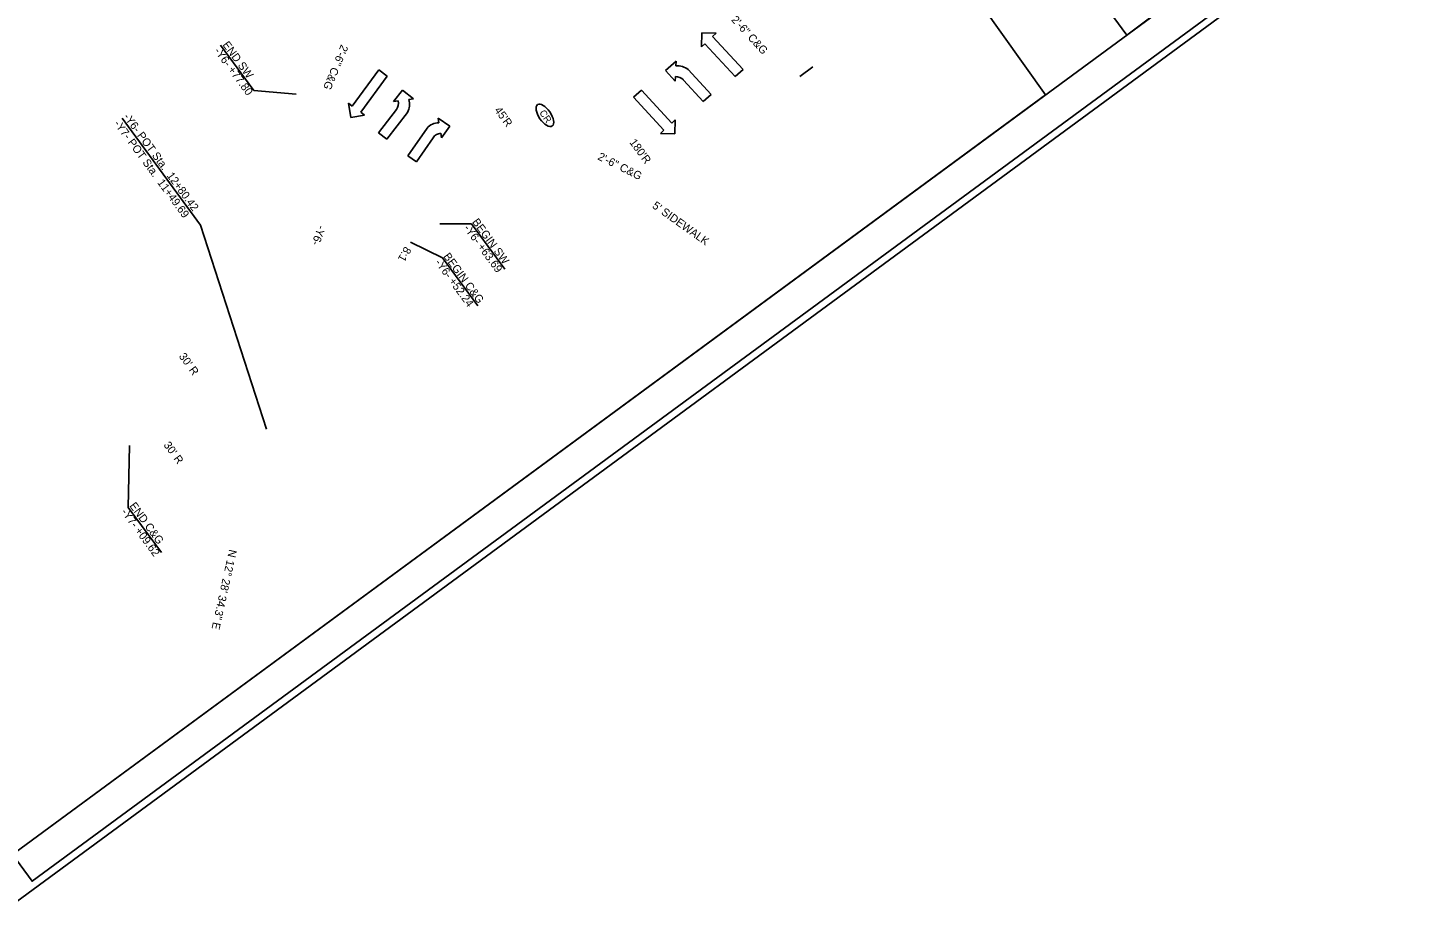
# Model space of a CAD drawing. Extents: x 1763480 to 1764420, y 711010 to 712012.
# Drawn here: x 1763983.9 to 1764419.6, y 711009.7 to 711284 of the extents above; entities that cross this region are included whole.
import ezdxf

# ---------------------------------------------------------------- set-up
doc = ezdxf.new("R2010")
doc.units = 0
for name, color, linetype in [('Old_Level_40', 7, 'Continuous'), ('P-WATER', 7, 'Continuous'), ('Prop Conc 4in Sidewalk', 7, 'Continuous'), ('Prop Grid Mask', 7, 'Continuous'), ('Prop Horizontal Alignment Direction Label', 7, 'Continuous'), ('Prop Horizontal Alignment Station Label', 7, 'Continuous'), ('Prop Lane Arrow CELL', 7, 'Continuous'), ('Prop Rem of Exist Asph Pvmt', 7, 'Continuous'), ('Prop WCC CELL', 7, 'Continuous'), ('Sheet Plot Border Inside CELL', 7, 'Continuous'), ('Sheet Plot Border Outside CELL', 7, 'Continuous')]:
    doc.layers.add(name, color=color, linetype=linetype)

msp = doc.modelspace()

# ---------------------------------------------------------------- linework, layer by layer
at = {"layer": 'Old_Level_40'}
msp.add_lwpolyline([(1764268.03, 711362.41), (1764327.28, 711281.82), (1764337.34, 711289.22), (1764278.09, 711369.81)], close=True, dxfattribs=at)
at = {"layer": 'P-WATER'}
msp.add_lwpolyline([(1764402.04, 711336.79), (1763957.77, 711941.04), (1763535.55, 711630.61), (1763979.82, 711026.35)], close=True, dxfattribs=at)
at = {"layer": 'Prop Conc 4in Sidewalk'}
for p, q in [((1764054.55, 711264.47), (1764044.08, 711278.68)), ((1764229.23, 711271.84), (1764225.17, 711268.86)), ((1764067.74, 711263.33), (1764054.55, 711264.47)), ((1764112.66, 711222.84), (1764122.54, 711222.83)), ((1764132.94, 711208.71), (1764122.54, 711222.83))]:
    msp.add_line(p, q, dxfattribs=at)
at = {"layer": 'Prop Grid Mask'}
for p, q in [((1764103.49, 711217.08), (1764113.47, 711212.24)), ((1764124.53, 711197.23), (1764113.47, 711212.24)), ((1764015.23, 711134.25), (1764015.67, 711153.55)), ((1764025.63, 711120.13), (1764015.23, 711134.25))]:
    msp.add_line(p, q, dxfattribs=at)
at = {"layer": 'Prop Horizontal Alignment Station Label'}
msp.add_lwpolyline([(1763957.77, 711941.04), (1764052.94, 711811.6), (1764008.24, 711778.74), (1764295.85, 711387.56), (1764241.65, 711347.71), (1764301.88, 711263.14), (1763979.82, 711026.35), (1763792.92, 711280.55), (1763982.56, 711419.98), (1763871.46, 711571.1), (1763681.82, 711431.66), (1763535.55, 711630.61)], close=True, dxfattribs=at)
at = {"layer": 'Prop Lane Arrow CELL'}
for p, q in [((1764194.37, 711278.09), (1764194.51, 711282.51)), ((1764195.47, 711279.11), (1764194.37, 711278.09)), ((1764194.51, 711282.51), (1764199, 711282.36)), ((1764204.96, 711268.82), (1764195.47, 711279.11)), ((1764199, 711282.36), (1764197.9, 711281.35)), ((1764197.9, 711281.35), (1764207.39, 711271.05)), ((1764085.28, 711259.64), (1764093.55, 711270.93)), ((1764085.28, 711259.64), (1764093.55, 711270.93)), ((1764093.55, 711270.93), (1764096.22, 711268.98)), ((1764093.55, 711270.93), (1764096.22, 711268.98)), ((1764186.45, 711273.64), (1764183.17, 711270.7)), ((1764183.17, 711270.7), (1764186.17, 711267.35)), ((1764186.39, 711272.15), (1764186.45, 711273.64)), ((1764197.38, 711263.24), (1764190.26, 711271.02)), ((1764207.39, 711271.05), (1764204.96, 711268.82)), ((1764096.22, 711268.98), (1764087.94, 711257.69)), ((1764096.22, 711268.98), (1764087.94, 711257.69)), ((1764186.17, 711267.35), (1764186.24, 711268.83)), ((1764188.77, 711267.76), (1764194.95, 711261.01)), ((1764100.95, 711264.58), (1764098.18, 711261.04)), ((1764100.95, 711264.58), (1764098.18, 711261.04)), ((1764098.18, 711261.04), (1764099.65, 711261.23)), ((1764098.18, 711261.04), (1764099.65, 711261.23)), ((1764104.42, 711261.88), (1764100.95, 711264.58)), ((1764104.42, 711261.88), (1764100.95, 711264.58)), ((1764102.94, 711261.68), (1764104.42, 711261.88)), ((1764102.94, 711261.68), (1764104.42, 711261.88)), ((1764173.19, 711262.36), (1764175.62, 711264.6)), ((1764182.68, 711252.07), (1764173.19, 711262.36)), ((1764175.62, 711264.6), (1764185.11, 711254.3)), ((1764194.95, 711261.01), (1764197.38, 711263.24)), ((1764084.79, 711256.09), (1764084.07, 711260.52)), ((1764084.07, 711260.52), (1764085.28, 711259.64)), ((1764084.79, 711256.09), (1764084.07, 711260.52)), ((1764084.07, 711260.52), (1764085.28, 711259.64)), ((1764089.15, 711256.8), (1764084.79, 711256.09)), ((1764089.15, 711256.8), (1764084.79, 711256.09)), ((1764087.94, 711257.69), (1764089.15, 711256.8)), ((1764087.94, 711257.69), (1764089.15, 711256.8)), ((1764099.05, 711258.55), (1764093.5, 711251.27)), ((1764099.05, 711258.55), (1764093.5, 711251.27)), ((1764096.13, 711249.27), (1764102.52, 711257.66)), ((1764096.13, 711249.27), (1764102.52, 711257.66)), ((1764102.61, 711244.11), (1764108.65, 711252.76)), ((1764102.61, 711244.11), (1764108.65, 711252.76)), ((1764112.34, 711254.39), (1764112.08, 711255.85)), ((1764112.08, 711255.85), (1764115.72, 711253.38)), ((1764112.34, 711254.39), (1764112.08, 711255.85)), ((1764112.08, 711255.85), (1764115.72, 711253.38)), ((1764115.72, 711253.38), (1764113.19, 711249.66)), ((1764115.72, 711253.38), (1764113.19, 711249.66)), ((1764185.11, 711254.3), (1764186.21, 711255.32)), ((1764186.21, 711255.32), (1764186.06, 711250.9)), ((1764093.5, 711251.27), (1764096.13, 711249.27)), ((1764093.5, 711251.27), (1764096.13, 711249.27)), ((1764110.55, 711249.73), (1764105.32, 711242.22)), ((1764110.55, 711249.73), (1764105.32, 711242.22)), ((1764113.19, 711249.66), (1764112.93, 711251.12)), ((1764113.19, 711249.66), (1764112.93, 711251.12)), ((1764181.58, 711251.05), (1764182.68, 711252.07)), ((1764186.06, 711250.9), (1764181.58, 711251.05)), ((1764105.32, 711242.22), (1764102.61, 711244.11)), ((1764105.32, 711242.22), (1764102.61, 711244.11))]:
    msp.add_line(p, q, dxfattribs=at)
for centre, radius, start, end in [((1764186.98, 711266.95), 5.25, 51.1244, 96.4361), ((1764186.36, 711265.57), 3.27, 42.4483, 92.1065), ((1764096.46, 711260.53), 3.28, 322.6881, 12.3463), ((1764096.46, 711260.53), 3.28, 322.6881, 12.3463), ((1764097.93, 711260.17), 5.25, 331.3642, 16.6759), ((1764097.93, 711260.17), 5.25, 331.3642, 16.6759), ((1764112.44, 711249.15), 5.25, 91.1316, 136.4433), ((1764112.44, 711249.15), 5.25, 91.1316, 136.4433), ((1764113.23, 711247.87), 3.28, 95.4612, 145.1194), ((1764113.23, 711247.87), 3.28, 95.4612, 145.1194)]:
    msp.add_arc(centre, radius, start, end, dxfattribs=at)
at = {"layer": 'Prop Rem of Exist Asph Pvmt'}
for p, q in [((1764037.9, 711222.41), (1764013.33, 711255.84)), ((1764058.52, 711158.7), (1764037.9, 711222.41))]:
    msp.add_line(p, q, dxfattribs=at)
at = {"layer": 'Prop WCC CELL'}
msp.add_ellipse((1764145.46, 711256.73), major_axis=(2.29, -3.33), ratio=0.462467, dxfattribs=at)
at = {"layer": 'Sheet Plot Border Inside CELL'}
msp.add_lwpolyline([(1763491.78, 711688.55), (1763985.22, 711017.43), (1764410.21, 711329.9), (1763916.77, 712001.02)], close=True, dxfattribs=at)
at = {"layer": 'Sheet Plot Border Outside CELL'}
msp.add_lwpolyline([(1763479.87, 711687.86), (1763978.5, 711009.69), (1764419.6, 711334.01), (1763920.98, 712012.18)], close=True, dxfattribs=at)

# ---------------------------------------------------------------- texts
at = {"layer": 'Prop Conc 4in Sidewalk'}
for s, rotation, p in [('END SW', 306.3875, (1764044.61, 711278.74)), ('-Y6- +77.80', 306.3875, (1764041.99, 711276.81)), ("5' SIDEWALK", 324.4352, (1764178.81, 711228.01)), ('-Y6- +63.69', 306.3875, (1764119.98, 711221.46)), ('BEGIN SW', 306.3875, (1764122.6, 711223.39))]:
    msp.add_text(s, height=2.5, rotation=rotation, dxfattribs=at).set_placement(p)
at = {"layer": 'Prop Grid Mask'}
for s, rotation, p in [('2\'-6" C&G', 312.4962, (1764203.54, 711286.45)), ('2\'-6" C&G', 247.5257, (1764081.81, 711279.02)), ("45'R", 306.325, (1764129.54, 711258.3)), ("180'R", 306.325, (1764171.76, 711248.26)), ('2\'-6" C&G', 333.4548, (1764161.76, 711243.05)), ('8:1', 240.7345, (1764101.71, 711215.94)), ('BEGIN C&G', 306.3875, (1764113.61, 711212.64)), ('-Y6- +52.24', 306.3875, (1764111, 711210.71)), ("30' R", 306.313, (1764030.96, 711181.43)), ("30' R", 306.313, (1764026.18, 711153.72)), ('END C&G', 306.3875, (1764015.53, 711134.72)), ('-Y7- +09.62', 306.3875, (1764012.92, 711132.79))]:
    msp.add_text(s, height=2.5, rotation=rotation, dxfattribs=at).set_placement(p)
at = {"layer": 'Prop Horizontal Alignment Direction Label'}
for s, rotation, p in [('-Y6-', 250.3603, (1764074.66, 711222.58)), ('N 12%%d 28\' 34.3" E', 257.5238, (1764046.8, 711121.26))]:
    msp.add_text(s, height=2.5, rotation=rotation, dxfattribs=at).set_placement(p)
at = {"layer": 'Prop Rem of Exist Asph Pvmt'}
for s, p in [('-Y6- POT Sta.  12+80.42', (1764013.63, 711256.27)), ('-Y7- POT Sta.  11+49.69', (1764010.68, 711254.11))]:
    msp.add_text(s, height=2.5, rotation=306.325, dxfattribs=at).set_placement(p)
at = {"layer": 'Prop WCC CELL'}
msp.add_text('CR', height=2.16, rotation=304.4873, dxfattribs=at).set_placement((1764143.62, 711257.52))

doc.saveas('drawing.dxf')
